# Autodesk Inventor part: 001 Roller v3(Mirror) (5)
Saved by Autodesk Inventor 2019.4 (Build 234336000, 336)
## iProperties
Created: 2020-06
Part Number: 001 Roller v3(Mirror) (5)
Material: Generic
Document SubType Name: Modeling
Designer: Administrator
Density: 1 g/cm^3
Appearance: Default
Title: 001 Roller v3(Mirror) (5)
Author: Administrator
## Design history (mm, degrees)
